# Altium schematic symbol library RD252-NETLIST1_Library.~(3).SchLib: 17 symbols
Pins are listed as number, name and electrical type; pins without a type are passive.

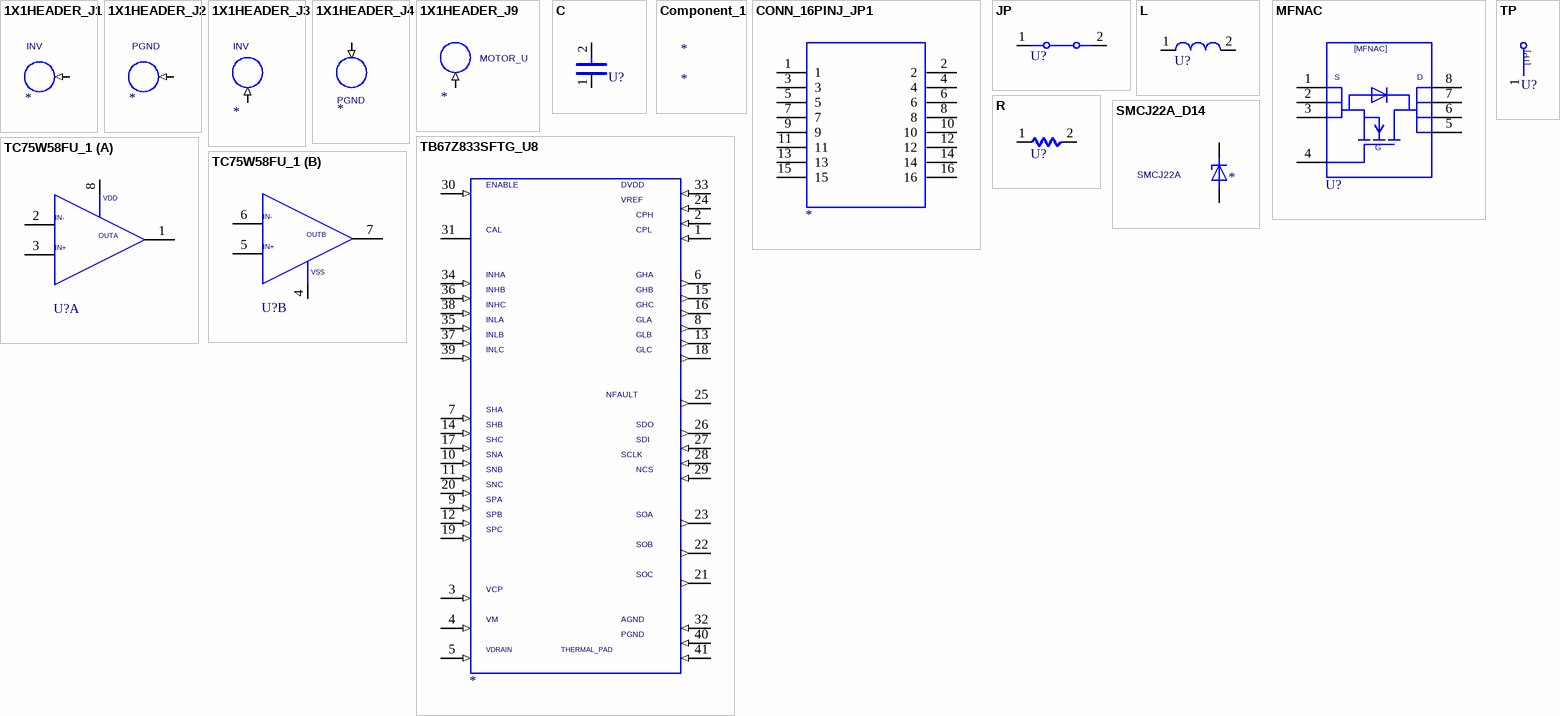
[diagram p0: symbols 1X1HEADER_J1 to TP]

## 1X1HEADER_J1
designator *, comment INV
TIME: 10:49:17; UPDATEUSER: t5459927; UPDATETIME: 11:39:32; SAVECOUNT: 4; GATENAME_1: G$1; SYMBOLNAME_1: 1HEADER; DEVICESETNAME: 1X1HEADER; COMP: 1X1HEADER_J1; ORIGIN: Altium; OriginalSymbolOrigin: (-5080,2540); Altium-Right: 20
pins: 1 (in)

## 1X1HEADER_J2
designator *, comment PGND
TIME: 10:49:18; UPDATEUSER: t5459927; UPDATETIME: 11:40:14; SAVECOUNT: 4; GATENAME_1: G$1; SYMBOLNAME_1: 1HEADER; DEVICESETNAME: 1X1HEADER; COMP: 1X1HEADER_J2; ORIGIN: Altium; OriginalSymbolOrigin: (-5080,2540); Altium-Right: 20
pins: 1 (in)

## 1X1HEADER_J3
designator *, comment INV
TIME: 10:49:12; UPDATEUSER: t5459927; UPDATETIME: 11:40:17; SAVECOUNT: 4; GATENAME_1: G$1; SYMBOLNAME_1: 1HEADER; DEVICESETNAME: 1X1HEADER; COMP: 1X1HEADER_J3; ORIGIN: Altium; OriginalSymbolOrigin: (-2540,5080); Altium-Right: 20
pins: 1 (in)

## 1X1HEADER_J4
designator *, comment PGND
TIME: 10:49:13; UPDATEUSER: t5459927; UPDATETIME: 11:40:20; SAVECOUNT: 4; GATENAME_1: G$1; SYMBOLNAME_1: 1HEADER; DEVICESETNAME: 1X1HEADER; COMP: 1X1HEADER_J4; ORIGIN: Altium; OriginalSymbolOrigin: (-2540,0); Altium-Right: 20
pins: 1 (in)

## 1X1HEADER_J9
designator *, comment MOTOR_U
TIME: 10:49:11; UPDATEUSER: t5459927; UPDATETIME: 11:40:23; SAVECOUNT: 4; GATENAME_1: G$1; SYMBOLNAME_1: 1HEADER; DEVICESETNAME: 1X1HEADER; COMP: 1X1HEADER_J9; ORIGIN: Altium; OriginalSymbolOrigin: (-2540,5080); Altium-Right: 20
pins: 1 (in)

## C
designator U?  (value not drawn)
TIME: 17:22:43; UPDATEUSER: t5459927; SAVECOUNT: 1; ORIGINALSYMBOLORIGIN: (-2540,5080); Altium-Right: 20; Altium-Bottom: 10
pins: 1, 2

## Component_1
designator *

## CONN_16PINJ_JP1
designator *, comment CONN_16PINJ  (value not drawn)
TIME: 10:49:14; UPDATEUSER: sptcae09; SAVECOUNT: 2; COMP: CONN_16PINJ_JP1; MP: TSM-108-01-L-DV; DEVICENAME: J; ORIGIN: Altium; MF: Samtec; GATENAME_1: A; OriginalSymbolOrigin: (0,0); Altium-Right: 80; Altium-Bottom: 110
pins: 1, 2, 3, 4, 5, 6, 7, 8, 9, 10, 11, 12, 13, 14, 15, 16

## JP
designator U?  (value not drawn)
OriginalSymbolOrigin: (2540,5080); Altium-Right: 40; Altium-Bottom: 20
pins: 1, 2

## L
designator U?  (value not drawn)
SAVECOUNT: 24; SAVEAREA0: -14227,-538,38802,29317; TIME: 11:19:06; UPDATEUSER: sptcae09; UPDATETIME: 15:04:42; COMP: 750315038; OriginalSymbolOrigin: (2540,5080); Altium-Right: 30; Altium-Bottom: 20
pins: 1, 2

## MFNAC
designator U?  (value not drawn)
TIME: 18:29:30; UPDATEUSER: 19990028; UPDATETIME: 14:45:16; SAVECOUNT: 26; SAVEAREA0: -10143,-336,37609,28718; OriginalSymbolOrigin: (5080,25400); Altium-Right: 70; Altium-Bottom: 90
pins: 1, 2, 3, 4, 5, 6, 7, 8

## R
designator U?  (value not drawn)
TIME: 17:22:43; UPDATEUSER: t5459927; SAVECOUNT: 1; ORIGINALSYMBOLORIGIN: (2540,2540); Altium-Right: 20
pins: 1, 2

## SMCJ22A_D14
designator *, comment SMCJ22A
TIME: 10:49:12; UPDATEUSER: sptcae09; UPDATETIME: 10:49:13; SAVECOUNT: 2; COMP: SMCJ22A_D14; ORIGIN: Altium; MF: Littelfuse; GATENAME_1: G$1; OriginalSymbolOrigin: (0,1270); Altium-Right: 20
pins: A, C

## TB67Z833SFTG_U8
designator *, comment DRV8323S  (value not drawn)
TIME: 10:49:18; UPDATEUSER: t5459927; UPDATETIME: 12:55:26; SAVECOUNT: 4; COMP: TB67Z833SFTG_U8; MP: DRV8323SRTAT; SYMBOLNAME_1: TB67Z833SFTG; ORIGIN: Altium; MF: Texas Instruments; GATENAME_1: G$1; OriginalSymbolOrigin: (0,0); Altium-Right: 140; Altium-Bottom: 330
pins: 1 (in), 2 (in), 3 (in), 4 (in), 5 (in), 6 (out), 7 (in), 8 (out), 9 (in), 10 (in), 11 (in), 12 (in), 13 (out), 14 (in), 15 (out), 16 (out), 17 (in), 18 (out), 19 (in), 20 (in), 21 (out), 22 (out), 23 (out), 24 (in), 25 (out), 26 (out), 27 (in), 28 (in), 29 (in), 30 (in), 31, 32 (in), 33 (in), 34 (in), 35 (in), 36 (in), 37 (in), 38 (in), 39 (in), 40 (in), 41 (in)

## TC75W58FU_1
designator U?, comment NA  (value not drawn)
TIME: 10:49:18; UPDATEUSER: t5459927; UPDATETIME: 18:58:17; SAVECOUNT: 8; GATENAME_1: G$1; SYMBOLNAME_1: TPH1R204PB; COMP: TC75W58FU_1; ORIGIN: Altium; OriginalSymbolOrigin: (0,0); Altium-Right: 60
part A pins: 1, 2, 3, 8
part B pins: 4, 5, 6, 7

## TP
designator U?  (value not drawn)
TIME: 16:12:21; UPDATEUSER: fukuda-y; UPDATETIME: 16:18:11; SAVECOUNT: 2; SAVEAREA0: -242,-92,12810,7836; OriginalSymbolOrigin: (0,7620); Altium-Right: 20; Altium-Bottom: 30
pins: 1

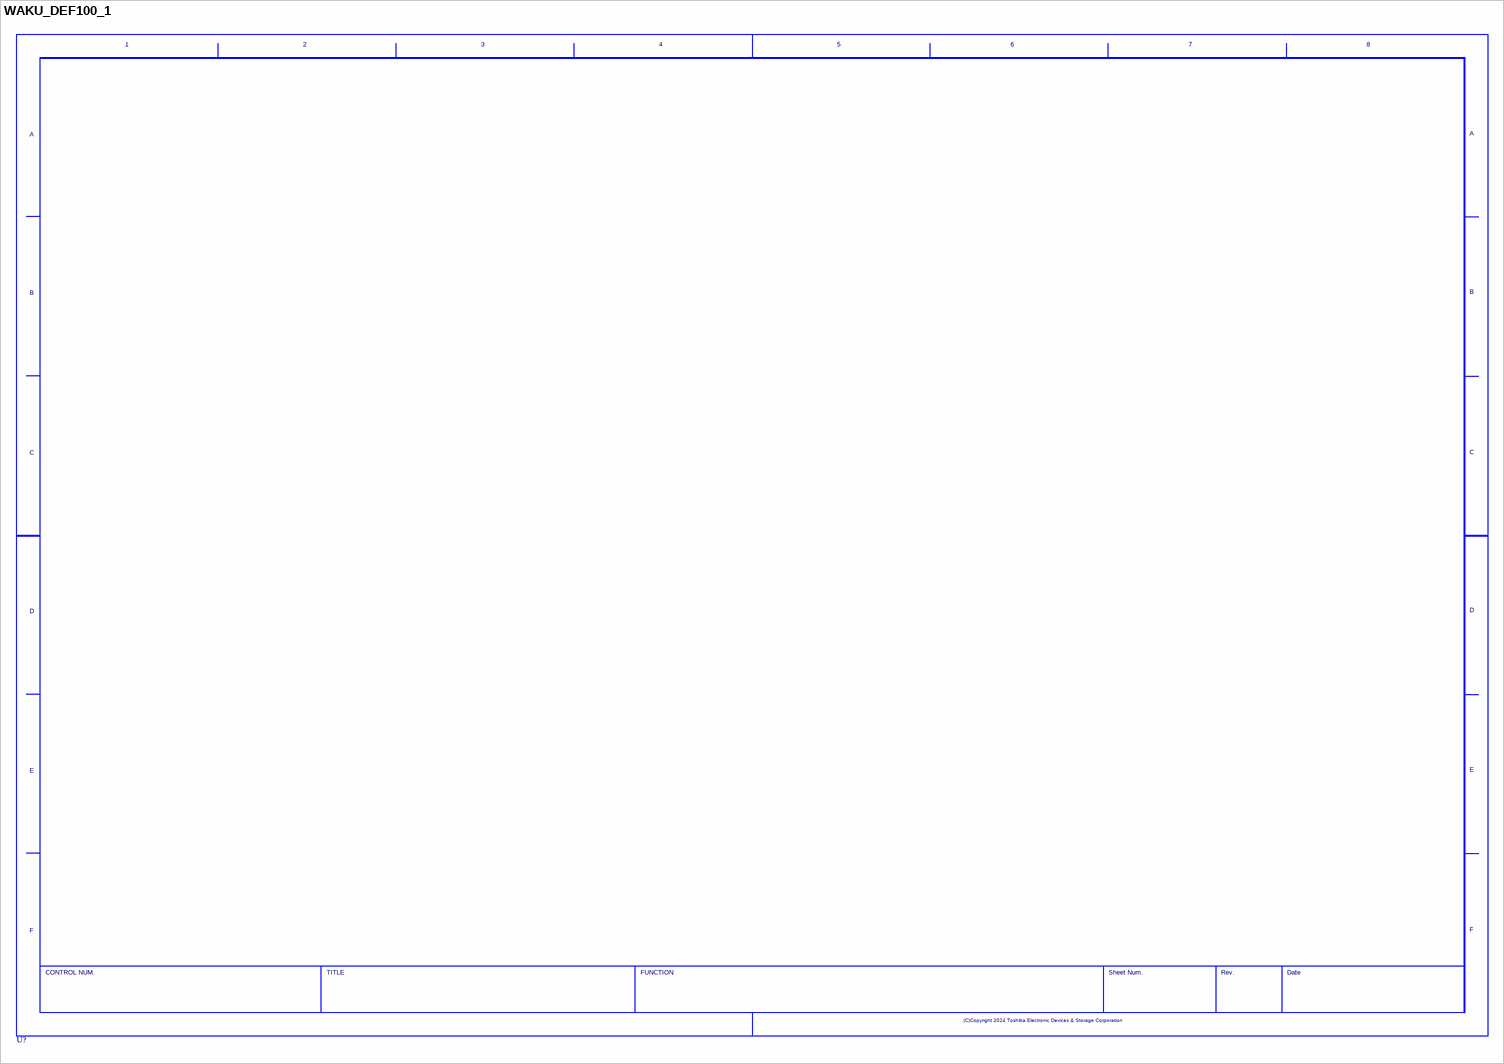
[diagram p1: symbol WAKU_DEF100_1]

## WAKU_DEF100_1
designator U?, comment WAKU_DEF100  (value not drawn)
TIME: 14:30:25; UPDATEUSER: cae; UPDATETIME: 18:29:18; SAVECOUNT: 3; PLOTTIME: HH:MM; SAVEAREA0: -63393,-16950,474261,314592; ORIGINALSYMBOLORIGIN: (0,0); Altium-Right: 1570; Altium-Bottom: 1070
